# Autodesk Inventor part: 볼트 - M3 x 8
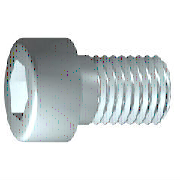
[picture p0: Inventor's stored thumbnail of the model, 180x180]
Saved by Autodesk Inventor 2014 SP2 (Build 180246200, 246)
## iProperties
IsCustomPart: 0
Created: 2012-02
Part Number: 볼트 - M3 x 8
Material: 스테인리스강
Description: 6각 소켓 머리 캡 나사
Document SubType Name: Modeling
Standard: ISO 4762
Designer: mduedu
Standard Revision: Fourth edition 2004-03-01
Standards Organization: ISO
Language: ko-KR
Size Designation: M3 x 8
Categories: <MemberInstance><Categories><Category DisplayName="조임쇠" InternalName="e4da775c-781d-43d5-af7c-5136215cf5a6" Mnemonic="FSTN"><Category DisplayName="볼트" InternalN
Density: 7.75 g/cm^3
Appearance: 반광택
Author: mduedu
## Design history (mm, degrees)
sketch "스케치1"
  geometry: L1 (-0.867, 0)-(8, 0); L2 (8, 0)-(8, 1.5); L3 (8, 1.5)-(1.25, 1.5); L4 (1.25, 1.5)-(0.943, 1.5); L5 (0.943, 1.5)-(0, 1.5); L6 (0, 1.5)-(0, 2.75); L7 (0, 2.75)-(-3, 2.75); L8 (-3, 2.75)-(-3, 1.443); L9 (-3, 1.443)-(-1.7, 1.443); L10 (-1.7, 1.443)-(-0.867, 0); L11 (-5.2, 0)-(10.2, 0) reference; L12 (0, -0.55)-(0, 3.3) reference; L13 (1.25, 1.5)-(0, 1.5)
  constraints: 22 end point, 6 parallel, 2 collinear, 2 perpendicular, 1 horizontal, 1 point on line
  dimensions: "d1" = 6.75 distance from line of L3.end L2 (= GEL); "d2" = 0.30683 distance of L4.end L3.end (computed from GAL); "d3" = 3 distance between parallel lines of L8 L6 (= KOH); "d4" = 1.3 distance of L8.end L9.end (= INTI); "d5" = 60 deg angle of L10 L1; "d6" = 3 diameter of L3 L1 (= GD); "d7" = 3 diameter of L5 L1 (= BDM); "d8" = 2.88675 diameter of L9 L1 (= 1.1547 x SW); "d9" = 5.5 diameter of L7 L1 (= KOD); "d26" = 8 distance between parallel lines of L12 L2 (= NLG)
revolve "본체" sketch "스케치1" stored, may be unused: angle "d10" = 90 deg
sketch "스케치2"
  geometry: L1 (0, -3.85)-(0, 3.85) reference; L2 (-3.85, 0)-(3.85, 0) reference; L3 (1.443, 0)-(0.722, -1.25); L4 (0.722, -1.25)-(-0.722, -1.25); L5 (-0.722, -1.25)-(-1.443, 0); L6 (-1.443, 0)-(-0.722, 1.25); L7 (-0.722, 1.25)-(0.722, 1.25); L8 (0.722, 1.25)-(1.443, 0); 2 further points
  constraints: 12 end point, 1 coincident, 1 horizontal alignment, 1 point on line, 12 other
extrude "슬롯" join sketch "스케치2" stored distance "d11" = 10; taper "d12" = 0 deg
workplane "Work Plane1"
fillet "Fillet2" dims "d30" = 0.1 (= R)
body "Solid1"
fillet "모깎기1" dims "d17" = 0.3 (= RR)
feature "스레드" dims "d13" = 6.75 (= GEL), "d14" = 0
chamfer "모따기1" distance "d15" = 0.30673 (= -0.5 x SPD + 0.5 x GD); stored, may be unused: second distance "d16" = 0.30673 (= GUL), angle "d27" = 45 deg
other parameters: "GD" = 3 [user parameter; used in 2 equation terms], "NLG" = 8 [user parameter; used in 1 equation term], "GEL" = 6.75 [user parameter; used in 2 equation terms], "KOD" = 5.5 [user parameter; used in 1 equation term], "KOH" = 3 [user parameter; used in 1 equation term], "INTI" = 1.3 [user parameter; used in 1 equation term], "GAL" = 0.30673 (= 0.61345 x PTC) [user parameter; used in 1 equation term], "GUL" = 0.30673 (= 0.61345 x PTC) [user parameter; used in 1 equation term], "BDM" = 3 (= NND) [user parameter; used in 1 equation term], "SW" = 2.5 [user parameter; used in 2 equation terms], "RR" = 0.3 [user parameter; used in 1 equation term], "SPD" = 2.38655 (= NND - 1.2269 x PTC) [user parameter; used in 1 equation term], "d19" = 0, "d28" = 0, "d29" = 0, "R" = 0.1 [user parameter; used in 1 equation term], "TOA" = 30 deg [user parameter], "GD1" = 2.38655 (= THREADDIA - 1.2269 x PTC) [user parameter], "THREADDIA" = 3 [user parameter; used in 1 equation term], "FAWI" = 45 deg [user parameter], "PTC" = 0.5 [user parameter; used in 5 equation terms], "NND" = 3 [user parameter; used in 2 equation terms], "E0" = 2.8875 (= 1.155 x SW) [user parameter]
